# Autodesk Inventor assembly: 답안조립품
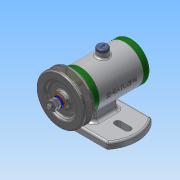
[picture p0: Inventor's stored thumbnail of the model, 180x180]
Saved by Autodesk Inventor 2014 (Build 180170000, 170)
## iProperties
Created: 2017-12
Part Number: 답안조립품
Document SubType Name: Assembly
Designer: user
Author: user
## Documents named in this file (14)
- C:\Users\user\Desktop\471207V1010\답안조립품.iam
- C:\Users\user\Desktop\471207V1010\본체.ipt
- C:\Users\user\Desktop\471207V1010\V벨트풀리.ipt
- C:\Users\user\Desktop\471207V1010\고무캡.ipt
- C:\Users\user\Desktop\471207V1010\너트 M 8.ipt
- C:\Users\user\Desktop\471207V1010\뒤커버.ipt
- C:\Users\user\Desktop\471207V1010\베어링 15 x 32 x 9.ipt
- C:\Users\user\Desktop\471207V1010\볼트 M4 x 12.ipt
- C:\Users\user\Desktop\471207V1010\스프링와셔 8.ipt
- C:\Users\user\Desktop\471207V1010\앞커버.ipt
- C:\Users\user\Desktop\471207V1010\오일 실 15 25 7.ipt
- C:\Users\user\Desktop\471207V1010\와셔 8x17.ipt
- C:\Users\user\Desktop\471207V1010\축.ipt
- C:\Users\user\Desktop\471207V1010\키 3 x 3 x 12.ipt
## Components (2 placed, 2 different names)
1. V벨트풀리:1
2. 고무캡:1
